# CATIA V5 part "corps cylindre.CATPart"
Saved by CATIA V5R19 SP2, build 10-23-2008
Part number: cylindre
Bounding box of the stored display mesh (mm): x -24.998 to 24.998, y -24.998 to 24.998, z 0 to 100
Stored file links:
  C:\Users\Romain\Documents\IFMA\2A\cours\S3\Projet CFAO-IAO\IAO\Catia\Cylindre\corps cylindre.CATPart
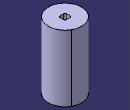
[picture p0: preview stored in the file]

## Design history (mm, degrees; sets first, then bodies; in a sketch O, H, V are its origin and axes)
Parameters
  L_cylindre = 100 mm
  R_cylindre = 15 mm
Body1 (main body)
  Sketch1 on yz-plane, origin (0, 0, 0), H (0, 1, 0), V (0, 0, 1)
    line L1 (0, 0) -> (25, 0)
    line L2 (25, 0) -> (25, 100)
    point P3 (0, 10)
    line L3 (0, 10) -> (15, 10)
    line L4 (15, 10) -> (15, 90)
    line L5 (15, 90) -> (0, 90)
    line L6 (25, 100) -> (0, 100)
    line L7 (0, 0) -> (0, 10)
    line L8 (0, 100) -> (0, 90)
    length L3 = 15 {= R_cylindre}
    length L4 = 80
    length L2 = 100 {= L_cylindre}
    distance L4 L2 = 10
    length L5 = 15 {= R_cylindre}
    length L8 = 10
    horizontal: L1 H, L3 H, L5 H, L6 H
    vertical: L2 V, L4 V, L7 V, L8 V
    coincidence: P3 V
  Shaft1: profile Sketch1, axis Sketch1.L7, angle 360
  Sketch2 on face of Shaft1 from Sketch1.L6, origin (0, 0, 100), H (1, 0, 0), V (0, 1, 0)
    line L1 (-5, 5) -> (5, 5)
    line L2 (5, 5) -> (5, -5)
    line L3 (5, -5) -> (-5, -5)
    line L4 (-5, -5) -> (-5, 5)
    length L2 = 10
    length L1 = 10
    distance O L1 = 5
    distance O L2 = 5
    horizontal: L1 H, L3 H
    vertical: L2 V, L4 V
  Pocket1: profile Sketch2, direction (0, 0, -1), through (limit type 6)
  Fillet1: radius 2, on edge [face of Pocket1 from Sketch2.L1 | face of Pocket1 from Sketch2.L2]
  Fillet2: radius 2, on edge [face of Pocket1 from Sketch2.L4 | face of Pocket1 from Sketch2.L1]
  Fillet3: radius 2, on edge [face of Pocket1 from Sketch2.L3 | face of Pocket1 from Sketch2.L4]
  Fillet4: radius 2, on edge [face of Pocket1 from Sketch2.L2 | face of Pocket1 from Sketch2.L3]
